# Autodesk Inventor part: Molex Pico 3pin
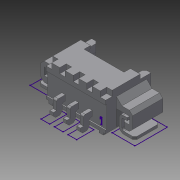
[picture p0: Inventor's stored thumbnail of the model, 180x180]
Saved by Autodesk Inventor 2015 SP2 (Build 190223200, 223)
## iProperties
Created: 2015-09
Part Number: Molex Pico 3pin
Material: Allgemein
Document SubType Name: Modeling
Designer: rYan
Density: 1 g/cm^3
Appearance: Vorgabe
Author: rYan
Author: me
Title: 532610371
Sending System: PRO/ENGINEER BY PARAMETRIC TECHNOLOGY CORPORATION, 2011490
Preprocessor: PRO/ENGINEER BY PARAMETRIC TECHNOLOGY CORPORATION, 2011490
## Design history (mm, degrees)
node "5326103711"
  sketch "3D-Skizze1"
node "Volumenkörper1"
node "Basis1"
